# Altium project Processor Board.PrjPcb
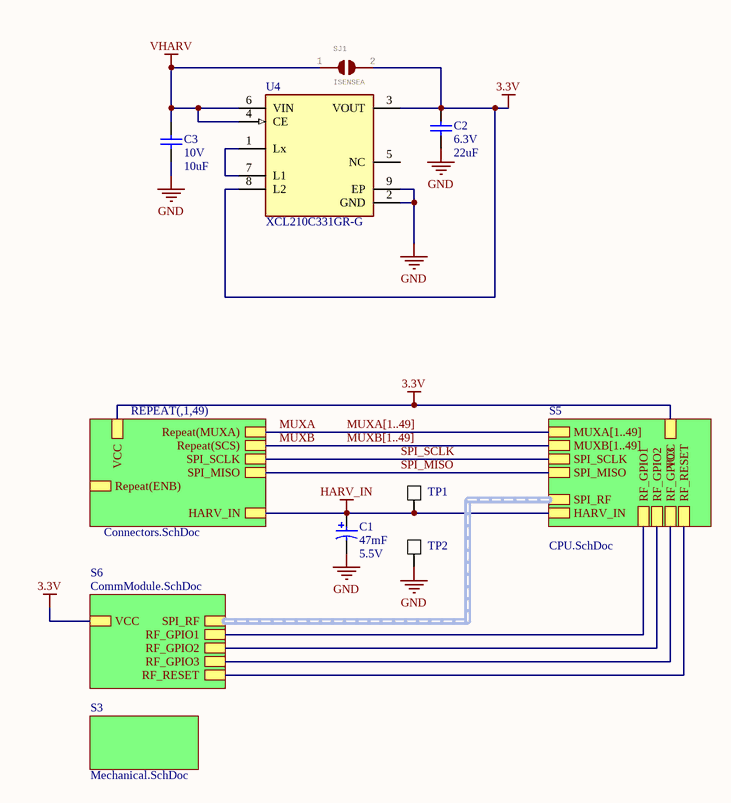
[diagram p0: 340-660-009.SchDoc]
ASSM_PN: Set In Variant; BOM_REV: 1.0.0; DOC_NUM: 340-660-009; DOC_REV: 1.0.0; PCB_PN: 21000-1011
5 sheets, 186 parts. Net scope: hierarchical (ports join the sheet entries above them; power ports are global).
Board file: 340-660-009.PcbDoc
Sheets:
  340-660-009.SchDoc
    S3 = Mechanical.SchDoc
    1 = Connectors.SchDoc
    2 = Connectors.SchDoc
    3 = Connectors.SchDoc
    4 = Connectors.SchDoc
    5 = Connectors.SchDoc
    6 = Connectors.SchDoc
    7 = Connectors.SchDoc
    8 = Connectors.SchDoc
    9 = Connectors.SchDoc
    10 = Connectors.SchDoc
    11 = Connectors.SchDoc
    12 = Connectors.SchDoc
    13 = Connectors.SchDoc
    14 = Connectors.SchDoc
    15 = Connectors.SchDoc
    16 = Connectors.SchDoc
    17 = Connectors.SchDoc
    18 = Connectors.SchDoc
    19 = Connectors.SchDoc
    20 = Connectors.SchDoc
    21 = Connectors.SchDoc
    22 = Connectors.SchDoc
    23 = Connectors.SchDoc
    24 = Connectors.SchDoc
    25 = Connectors.SchDoc
    26 = Connectors.SchDoc
    27 = Connectors.SchDoc
    28 = Connectors.SchDoc
    29 = Connectors.SchDoc
    30 = Connectors.SchDoc
    31 = Connectors.SchDoc
    32 = Connectors.SchDoc
    33 = Connectors.SchDoc
    34 = Connectors.SchDoc
    35 = Connectors.SchDoc
    36 = Connectors.SchDoc
    37 = Connectors.SchDoc
    38 = Connectors.SchDoc
    39 = Connectors.SchDoc
    40 = Connectors.SchDoc
    41 = Connectors.SchDoc
    42 = Connectors.SchDoc
    43 = Connectors.SchDoc
    44 = Connectors.SchDoc
    45 = Connectors.SchDoc
    46 = Connectors.SchDoc
    47 = Connectors.SchDoc
    48 = Connectors.SchDoc
    49 = Connectors.SchDoc
    S5 = CPU.SchDoc
    S6 = CommModule.SchDoc

## Sheet 340-660-009.SchDoc
size A; SheetNumber: 1; SheetTotal: 5

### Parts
C1  value 47mF  Voltage: 5.5V  [CAP_KEM_S6011_FC]  (hidden comment: FCS0H473ZFTBR24)
C2  value 22uF  Voltage: 6.3V  [0402CAP]  (hidden comment: CL05A226MQ6ZUN8)
C3  value 10uF  Voltage: 10V  [0402CAP]  (hidden comment: CL05A106MP5NUNC)
SJ1  ISENSEA  [SOLDERJUMPER_ARROW_NOPASTE]  (no BOM)
TP1  TEST POINT  [TP1-s]  (value not drawn)  (no BOM)
TP2  TEST POINT  [TP1-s]  (value not drawn)  (no BOM)
U4  XCL210C331GR-G  [XCL210C331GRG]

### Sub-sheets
REPEAT(,1,49) = Connectors.SchDoc: Repeat(MUXA), HARV_IN, VCC, Repeat(ENB), Repeat(SCS), SPI_SCLK, SPI_MISO
S3 = Mechanical.SchDoc: no entries
S5 = CPU.SchDoc: VCC, SPI_RF (harness SPI), HARV_IN, MUXA[1..49], MUXB[1..49], SPI_SCLK, SPI_MISO, RF_GPIO1, RF_GPIO2, RF_GPIO3, RF_RESET
S6 = CommModule.SchDoc: VCC, SPI_RF (harness SPI), RF_GPIO1, RF_GPIO2, RF_GPIO3, RF_RESET

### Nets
3.3V: C2.2 SJ1.2 U4.3(VOUT) U4.8(L2) ; sheet REPEAT(,1,49)/VCC, sheet S5/VCC, sheet S6/VCC  [project net V3.3V]
GND: C1.- C2.1 C3.1 TP2.1(A) U4.2(GND) U4.9(EP)
HARV_IN: C1.+ TP1.1(A) ; sheet REPEAT(,1,49)/HARV_IN, sheet S5/HARV_IN
VHARV: C3.2 SJ1.1 U4.4(CE) U4.6(VIN)
DIO1: sheet S5/RF_GPIO3, sheet S6/RF_GPIO3
DIO2: sheet S5/RF_GPIO2, sheet S6/RF_GPIO2
DIO3: sheet S5/RF_GPIO1, sheet S6/RF_GPIO1
nRESET: sheet S5/RF_RESET, sheet S6/RF_RESET
SPI_MISO: sheet REPEAT(,1,49)/SPI_MISO, sheet S5/SPI_MISO
SPI_SCLK: sheet REPEAT(,1,49)/SPI_SCLK, sheet S5/SPI_SCLK
NetU4_1: U4.1(Lx) U4.7(L1)

Not connected (* = marked no-connect by the designer): U4 5(NC)

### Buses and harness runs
bus MUXA[1..49] = sheet S5/MUXA[1..49]
bus MUXB[1..49] = sheet S5/MUXB[1..49]
harness sheet S5/SPI_RF = sheet S6/SPI_RF

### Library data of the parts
C1 = CAP_Supercap_47mF_5.5V_FCS0H473ZFTBR24: 47 mF (EDLC) Supercapacitor 5.5 V Radial, Can - SMD 100Ohm @ 1kHz; Mfg: Kemet; ADSP_PN: 17015-???
C2 = CAP_0402_22uF_X5R_6.3V: 22µF ±20% 6.3V Ceramic Capacitor X5R 0402 (1005 Metric); ADSP_PN: 01020-158; Mfg: Samsung
C3 = CAP_0402_10uF_X5R_10V: CAP CER 10UF 10V X5R 0402; ADSP_PN: 01020-053; Mfg: Samsung; Type: CAPACITOR
SJ1 = SOLDERJUMPER_OPEN: SMD Solder JUMPER   Solder the two pads together to create a connection, or remove the solder to break it.REFLOW - Use this footprint for solder paste and reflow ovens. WAVE - Use this footprint for hand-soldering (larger pads).    CLOSED - Has a trace between the two pads to ensure it is closed by default.  The trace needs to be cut to disable the jumper, and can be closed again by creating a solder bridge between the two pads.; GateName_1: 1; BOM: EXCLUDE
TP1 TP2 = Test_Point_SMT: Test Point SMT
U4 = XCL210C331GR-G: DC/DC CONV, 3.3V, 0.2A, 85DEG C ROHS COMPLIANT: YES; Mfg: Torex

## Sheet Mechanical.SchDoc
size A; SheetNumber: 2; SheetTotal: 5
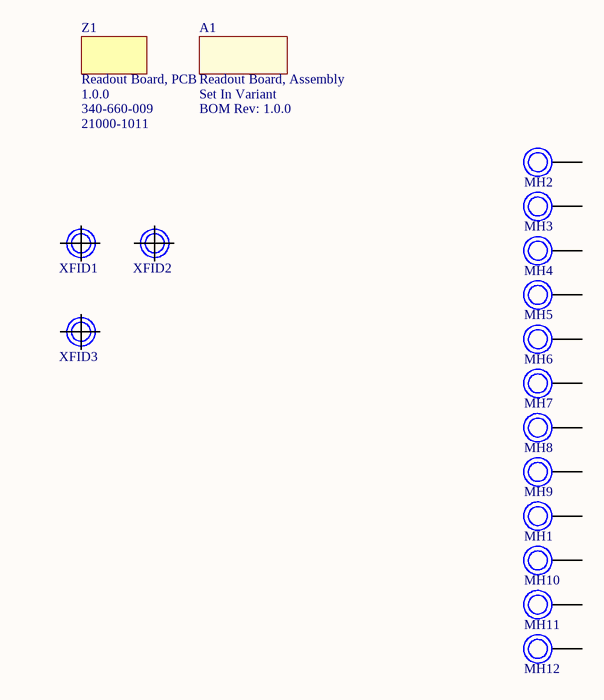
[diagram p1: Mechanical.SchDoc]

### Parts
A1  Readout Board, Assembly  BOM Rev: 1.0.0  ADSP_PN: Set In Variant  (mechanical)
MH1  Mounting Hole  [MH_2MM]  (value not drawn)  (no BOM)
MH2  Mounting Hole  [MH_2MM]  (value not drawn)  (no BOM)
MH3  Mounting Hole  [MH_2MM]  (value not drawn)  (no BOM)
MH4  Mounting Hole  [MH_2MM]  (value not drawn)  (no BOM)
MH5  Mounting Hole  [MH_2MM]  (value not drawn)  (no BOM)
MH6  Mounting Hole  [MH_2MM]  (value not drawn)  (no BOM)
MH7  Mounting Hole  [MH_2MM]  (value not drawn)  (no BOM)
MH8  Mounting Hole  [MH_2MM]  (value not drawn)  (no BOM)
MH9  Mounting Hole  [MH_2MM]  (value not drawn)  (no BOM)
MH10  Mounting Hole  [MH_2MM]  (value not drawn)  (no BOM)
MH11  Mounting Hole  [MH_2MM]  (value not drawn)  (no BOM)
MH12  Mounting Hole  [MH_2MM]  (value not drawn)  (no BOM)
XFID1  (no value)  [FID_TOP_BOT_39]
XFID2  (no value)  [FID_TOP_BOT_39]
XFID3  (no value)  [FID_TOP_BOT_39]
Z1  Readout Board, PCB  Rev: 1.0.0  DocNum: 340-660-009  ADSP_PN: 21000-1011  (mechanical)

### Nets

Not connected (* = marked no-connect by the designer): MH1 1; MH2 1; MH3 1; MH4 1; MH5 1; MH6 1; MH7 1; MH8 1; MH9 1; MH10 1; MH11 1; MH12 1

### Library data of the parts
A1 = PCB_Assembly: DocNum: 340-660-009
MH1-MH12 = MountingHole
XFID1-XFID3 = MOUNT_FIDUCIAL: Mounting Hole
Z1 = PCB_Rigid: RIGID PCB;  BARE

## Sheet Connectors.SchDoc
size A; SheetNumber: 4; SheetTotal: 5
Used 49 times, as channels 1, 2, 3, 4, 5, 6, 7, 8, 9, 10, 11, 12, 13, 14, 15, 16, 17, 18, 19, 20, 21, 22, 23, 24, 25, 26, 27, 28, 29, 30, 31, 32, 33, 34, 35, 36, 37, 38, 39, 40, 41, 42, 43, 44, 45, 46, 47, 48, 49. Parts and nets are listed once, with the designators drawn on the sheet.
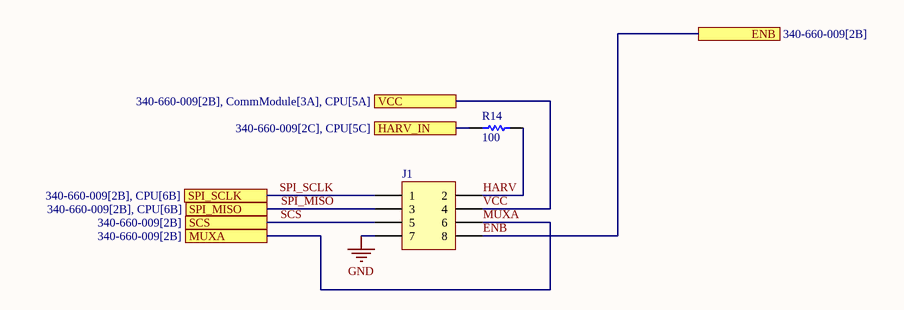
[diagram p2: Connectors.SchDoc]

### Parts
J1  (no value)  [CONN_SAMTEC_FTS-104-01-L-DV]
R14  value 100  [0402RES]  (hidden comment: RC0402FR-07100RL)

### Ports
ENB (see 340-660-009[2B]), HARV_IN (see 340-660-009[2C], CPU[5C]), MUXA (see 340-660-009[2B]), SCS (see 340-660-009[2B]), SPI_MISO (see 340-660-009[2B], CPU[6B]), SPI_SCLK (see 340-660-009[2B], CPU[6B]), VCC (see 340-660-009[2B], CommModule[3A], CPU[5A])

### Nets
GND: J1.7
ENB: J1.8 ; port ENB
HARV: J1.2 R14.1
HARV_IN: R14.2 ; port HARV_IN
MUXA: J1.6 ; port MUXA
SCS: J1.5 ; port SCS
SPI_MISO: J1.3 ; port SPI_MISO
SPI_SCLK: J1.1 ; port SPI_SCLK
VCC: J1.4 ; port VCC

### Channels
1: designators J1=J2#1 R14=R4#1; ports ENB=ENB_1 HARV_IN=HARV_IN MUXA=MUXA SCS=MUXB1 SPI_MISO=SPI_MISO SPI_SCLK=SPI_SCLK VCC=V3.3V
2: designators J1=J3#1 R14=R5#1; ports ENB=ENB_2 HARV_IN=HARV_IN MUXA=MUXA SCS=MUXB2 SPI_MISO=SPI_MISO SPI_SCLK=SPI_SCLK VCC=V3.3V
3: designators J1=J4#1 R14=R6; ports ENB=ENB_3 HARV_IN=HARV_IN MUXA=MUXA SCS=MUXB3 SPI_MISO=SPI_MISO SPI_SCLK=SPI_SCLK VCC=V3.3V
4: designators J1=J5#1 R14=R7; ports ENB=ENB_4 HARV_IN=HARV_IN MUXA=MUXA SCS=MUXB4 SPI_MISO=SPI_MISO SPI_SCLK=SPI_SCLK VCC=V3.3V
5: designators J1=J6 R14=R8#1; ports ENB=ENB_5 HARV_IN=HARV_IN MUXA=MUXA SCS=MUXB5 SPI_MISO=SPI_MISO SPI_SCLK=SPI_SCLK VCC=V3.3V
6: designators J1=J7 R14=R9#1; ports ENB=ENB_6 HARV_IN=HARV_IN MUXA=MUXA SCS=MUXB6 SPI_MISO=SPI_MISO SPI_SCLK=SPI_SCLK VCC=V3.3V
7: designators J1=J8 R14=R10#1; ports ENB=ENB_7 HARV_IN=HARV_IN MUXA=MUXA SCS=MUXB7 SPI_MISO=SPI_MISO SPI_SCLK=SPI_SCLK VCC=V3.3V
8: designators J1=J9 R14=R11; ports ENB=ENB_8 HARV_IN=HARV_IN MUXA=MUXA SCS=MUXB8 SPI_MISO=SPI_MISO SPI_SCLK=SPI_SCLK VCC=V3.3V
9: designators J1=J10 R14=R12; ports ENB=ENB_9 HARV_IN=HARV_IN MUXA=MUXA SCS=MUXB9 SPI_MISO=SPI_MISO SPI_SCLK=SPI_SCLK VCC=V3.3V
10: designators J1=J11 R14=R13; ports ENB=ENB_10 HARV_IN=HARV_IN MUXA=MUXA SCS=MUXB10 SPI_MISO=SPI_MISO SPI_SCLK=SPI_SCLK VCC=V3.3V
11: designators J1=J12 R14=R14; ports ENB=ENB_11 HARV_IN=HARV_IN MUXA=MUXA SCS=MUXB11 SPI_MISO=SPI_MISO SPI_SCLK=SPI_SCLK VCC=V3.3V
12: designators J1=J13 R14=R15; ports ENB=ENB_12 HARV_IN=HARV_IN MUXA=MUXA SCS=MUXB12 SPI_MISO=SPI_MISO SPI_SCLK=SPI_SCLK VCC=V3.3V
13: designators J1=J14 R14=R16; ports ENB=ENB_13 HARV_IN=HARV_IN MUXA=MUXA SCS=MUXB13 SPI_MISO=SPI_MISO SPI_SCLK=SPI_SCLK VCC=V3.3V
14: designators J1=J15 R14=R17; ports ENB=ENB_14 HARV_IN=HARV_IN MUXA=MUXA SCS=MUXB14 SPI_MISO=SPI_MISO SPI_SCLK=SPI_SCLK VCC=V3.3V
15: designators J1=J16 R14=R18; ports ENB=ENB_15 HARV_IN=HARV_IN MUXA=MUXA SCS=MUXB15 SPI_MISO=SPI_MISO SPI_SCLK=SPI_SCLK VCC=V3.3V
16: designators J1=J17 R14=R19; ports ENB=ENB_16 HARV_IN=HARV_IN MUXA=MUXA SCS=MUXB16 SPI_MISO=SPI_MISO SPI_SCLK=SPI_SCLK VCC=V3.3V
17: designators J1=J18 R14=R20; ports ENB=ENB_17 HARV_IN=HARV_IN MUXA=MUXA SCS=MUXB17 SPI_MISO=SPI_MISO SPI_SCLK=SPI_SCLK VCC=V3.3V
18: designators J1=J19 R14=R21; ports ENB=ENB_18 HARV_IN=HARV_IN MUXA=MUXA SCS=MUXB18 SPI_MISO=SPI_MISO SPI_SCLK=SPI_SCLK VCC=V3.3V
19: designators J1=J20 R14=R22; ports ENB=ENB_19 HARV_IN=HARV_IN MUXA=MUXA SCS=MUXB19 SPI_MISO=SPI_MISO SPI_SCLK=SPI_SCLK VCC=V3.3V
20: designators J1=J21 R14=R23; ports ENB=ENB_20 HARV_IN=HARV_IN MUXA=MUXA SCS=MUXB20 SPI_MISO=SPI_MISO SPI_SCLK=SPI_SCLK VCC=V3.3V
21: designators J1=J22 R14=R24; ports ENB=ENB_21 HARV_IN=HARV_IN MUXA=MUXA SCS=MUXB21 SPI_MISO=SPI_MISO SPI_SCLK=SPI_SCLK VCC=V3.3V
22: designators J1=J23 R14=R25; ports ENB=ENB_22 HARV_IN=HARV_IN MUXA=MUXA SCS=MUXB22 SPI_MISO=SPI_MISO SPI_SCLK=SPI_SCLK VCC=V3.3V
23: designators J1=J24 R14=R26; ports ENB=ENB_23 HARV_IN=HARV_IN MUXA=MUXA SCS=MUXB23 SPI_MISO=SPI_MISO SPI_SCLK=SPI_SCLK VCC=V3.3V
24: designators J1=J25 R14=R27; ports ENB=ENB_24 HARV_IN=HARV_IN MUXA=MUXA SCS=MUXB24 SPI_MISO=SPI_MISO SPI_SCLK=SPI_SCLK VCC=V3.3V
25: designators J1=J26 R14=R28; ports ENB=ENB_25 HARV_IN=HARV_IN MUXA=MUXA SCS=MUXB25 SPI_MISO=SPI_MISO SPI_SCLK=SPI_SCLK VCC=V3.3V
26: designators J1=J27 R14=R29; ports ENB=ENB_26 HARV_IN=HARV_IN MUXA=MUXA SCS=MUXB26 SPI_MISO=SPI_MISO SPI_SCLK=SPI_SCLK VCC=V3.3V
27: designators J1=J28 R14=R30; ports ENB=ENB_27 HARV_IN=HARV_IN MUXA=MUXA SCS=MUXB27 SPI_MISO=SPI_MISO SPI_SCLK=SPI_SCLK VCC=V3.3V
28: designators J1=J29 R14=R31; ports ENB=ENB_28 HARV_IN=HARV_IN MUXA=MUXA SCS=MUXB28 SPI_MISO=SPI_MISO SPI_SCLK=SPI_SCLK VCC=V3.3V
29: designators J1=J30 R14=R32; ports ENB=ENB_29 HARV_IN=HARV_IN MUXA=MUXA SCS=MUXB29 SPI_MISO=SPI_MISO SPI_SCLK=SPI_SCLK VCC=V3.3V
30: designators J1=J31 R14=R33; ports ENB=ENB_30 HARV_IN=HARV_IN MUXA=MUXA SCS=MUXB30 SPI_MISO=SPI_MISO SPI_SCLK=SPI_SCLK VCC=V3.3V
31: designators J1=J32 R14=R34; ports ENB=ENB_31 HARV_IN=HARV_IN MUXA=MUXA SCS=MUXB31 SPI_MISO=SPI_MISO SPI_SCLK=SPI_SCLK VCC=V3.3V
32: designators J1=J33 R14=R35; ports ENB=ENB_32 HARV_IN=HARV_IN MUXA=MUXA SCS=MUXB32 SPI_MISO=SPI_MISO SPI_SCLK=SPI_SCLK VCC=V3.3V
33: designators J1=J34 R14=R36; ports ENB=ENB_33 HARV_IN=HARV_IN MUXA=MUXA SCS=MUXB33 SPI_MISO=SPI_MISO SPI_SCLK=SPI_SCLK VCC=V3.3V
34: designators J1=J35 R14=R37; ports ENB=ENB_34 HARV_IN=HARV_IN MUXA=MUXA SCS=MUXB34 SPI_MISO=SPI_MISO SPI_SCLK=SPI_SCLK VCC=V3.3V
35: designators J1=J36 R14=R38; ports ENB=ENB_35 HARV_IN=HARV_IN MUXA=MUXA SCS=MUXB35 SPI_MISO=SPI_MISO SPI_SCLK=SPI_SCLK VCC=V3.3V
36: designators J1=J37 R14=R39; ports ENB=ENB_36 HARV_IN=HARV_IN MUXA=MUXA SCS=MUXB36 SPI_MISO=SPI_MISO SPI_SCLK=SPI_SCLK VCC=V3.3V
37: designators J1=J38 R14=R40; ports ENB=ENB_37 HARV_IN=HARV_IN MUXA=MUXA SCS=MUXB37 SPI_MISO=SPI_MISO SPI_SCLK=SPI_SCLK VCC=V3.3V
38: designators J1=J39 R14=R41; ports ENB=ENB_38 HARV_IN=HARV_IN MUXA=MUXA SCS=MUXB38 SPI_MISO=SPI_MISO SPI_SCLK=SPI_SCLK VCC=V3.3V
39: designators J1=J40 R14=R42; ports ENB=ENB_39 HARV_IN=HARV_IN MUXA=MUXA SCS=MUXB39 SPI_MISO=SPI_MISO SPI_SCLK=SPI_SCLK VCC=V3.3V
40: designators J1=J41 R14=R43; ports ENB=ENB_40 HARV_IN=HARV_IN MUXA=MUXA SCS=MUXB40 SPI_MISO=SPI_MISO SPI_SCLK=SPI_SCLK VCC=V3.3V
41: designators J1=J42 R14=R44; ports ENB=ENB_41 HARV_IN=HARV_IN MUXA=MUXA SCS=MUXB41 SPI_MISO=SPI_MISO SPI_SCLK=SPI_SCLK VCC=V3.3V
42: designators J1=J43 R14=R45; ports ENB=ENB_42 HARV_IN=HARV_IN MUXA=MUXA SCS=MUXB42 SPI_MISO=SPI_MISO SPI_SCLK=SPI_SCLK VCC=V3.3V
43: designators J1=J44 R14=R46; ports ENB=ENB_43 HARV_IN=HARV_IN MUXA=MUXA SCS=MUXB43 SPI_MISO=SPI_MISO SPI_SCLK=SPI_SCLK VCC=V3.3V
44: designators J1=J45 R14=R47; ports ENB=ENB_44 HARV_IN=HARV_IN MUXA=MUXA SCS=MUXB44 SPI_MISO=SPI_MISO SPI_SCLK=SPI_SCLK VCC=V3.3V
45: designators J1=J46 R14=R48; ports ENB=ENB_45 HARV_IN=HARV_IN MUXA=MUXA SCS=MUXB45 SPI_MISO=SPI_MISO SPI_SCLK=SPI_SCLK VCC=V3.3V
46: designators J1=J47 R14=R49; ports ENB=ENB_46 HARV_IN=HARV_IN MUXA=MUXA SCS=MUXB46 SPI_MISO=SPI_MISO SPI_SCLK=SPI_SCLK VCC=V3.3V
47: designators J1=J48 R14=R50; ports ENB=ENB_47 HARV_IN=HARV_IN MUXA=MUXA SCS=MUXB47 SPI_MISO=SPI_MISO SPI_SCLK=SPI_SCLK VCC=V3.3V
48: designators J1=J49 R14=R51; ports ENB=ENB_48 HARV_IN=HARV_IN MUXA=MUXA SCS=MUXB48 SPI_MISO=SPI_MISO SPI_SCLK=SPI_SCLK VCC=V3.3V
49: designators J1=J51 R14=R56; ports ENB=ENB_49 HARV_IN=HARV_IN MUXA=MUXA SCS=MUXB49 SPI_MISO=SPI_MISO SPI_SCLK=SPI_SCLK VCC=V3.3V

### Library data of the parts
J1 = CONN_Samtec_FTS-104-01-L-DV: 2x4 0.050" Surface Mount Micro Terminal Strip; Positions: 6; Gender: MALE; Mfg: Samtec; Mfg_PN: FTS-103-01-L-DV; ADSP_PN: 03000-???
R14 = Res_0402_100_1%_1: RES SMD 100 OHM 1% 1/16W 0402; ADSP_PN: 00100-160; Mfg: Yageo

## Sheet CPU.SchDoc
size B; SheetNumber: 5; SheetTotal: 5
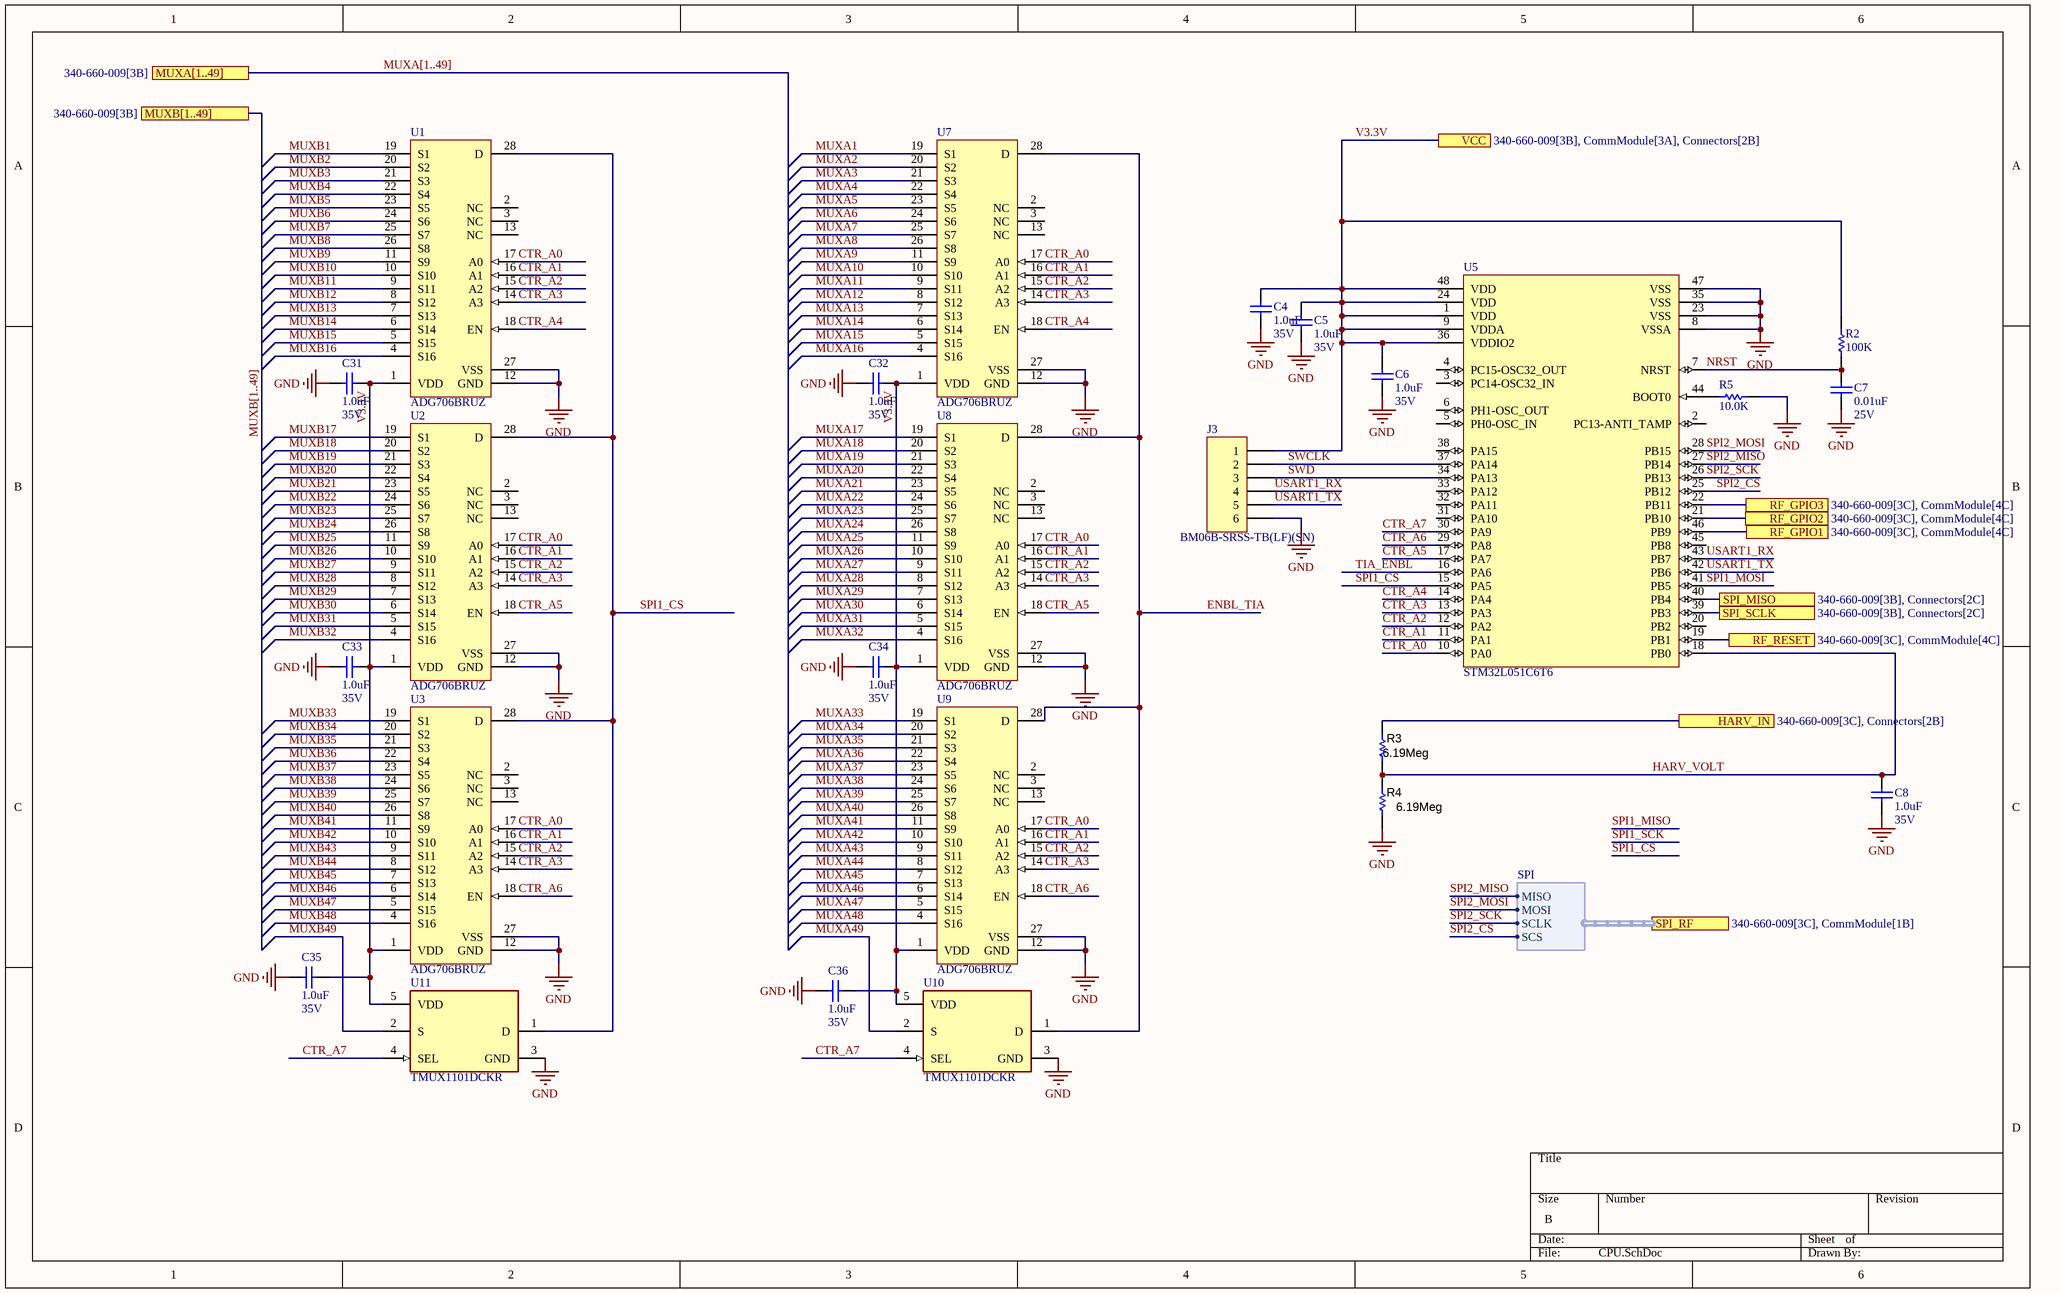
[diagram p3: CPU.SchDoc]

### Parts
(Parts that share a designator on the sheet are numbered #1, #2 ... from top to bottom, then left to right.)
C4  value 1.0uF  Voltage: 35V  [0402CAP]  (hidden comment: C1005X5R1V105K050BC)
C5  value 1.0uF  Voltage: 35V  [0402CAP]  (hidden comment: C1005X5R1V105K050BC)
C6  value 1.0uF  Voltage: 35V  [0402CAP]  (hidden comment: C1005X5R1V105K050BC)
C7  value 0.01uF  Voltage: 25V  [0402CAP]  (hidden comment: ECJ-0EB1E103K)
C8  value 1.0uF  Voltage: 35V  [0402CAP]  (hidden comment: C1005X5R1V105K050BC)
C31  value 1.0uF  Voltage: 35V  [0402CAP]  (hidden comment: C1005X5R1V105K050BC)
C32  value 1.0uF  Voltage: 35V  [0402CAP]  (hidden comment: C1005X5R1V105K050BC)
C33  value 1.0uF  Voltage: 35V  [0402CAP]  (hidden comment: C1005X5R1V105K050BC)
C34  value 1.0uF  Voltage: 35V  [0402CAP]  (hidden comment: C1005X5R1V105K050BC)
C35  value 1.0uF  Voltage: 35V  [0402CAP]  (hidden comment: C1005X5R1V105K050BC)
C36  value 1.0uF  Voltage: 35V  [0402CAP]  (hidden comment: C1005X5R1V105K050BC)
J3#2  BM06B-SRSS-TB(LF)(SN)  [JST_BM06B_TOP]
R2  value 100K  [0402RES]  (hidden comment: RC0402FR-07100KL)
R3  value 6.19Meg  [0402RES]
R4#2  value 6.19Meg  [0402RES]
R5#2  value 10.0K  [0402RES_SM]  (hidden comment: CRCW040210K0FKEDHP)
U1  ADG706BRUZ  [ADI-RU-28_L]
U2  ADG706BRUZ  [ADI-RU-28_L]
U3  ADG706BRUZ  [ADI-RU-28_L]
U5  STM32L051C6T6  [STM-LQFP48_N]
U7  ADG706BRUZ  [ADI-RU-28_L]
U8  ADG706BRUZ  [ADI-RU-28_L]
U9  ADG706BRUZ  [ADI-RU-28_L]
U10  TMUX1101DCKR  [FP-DCK0005A-IPC_B]
U11  TMUX1101DCKR  [FP-DCK0005A-IPC_B]

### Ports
HARV_IN (see 340-660-009[3C], Connectors[2B]), MUXA[1..49] (see 340-660-009[3B]), MUXB[1..49] (see 340-660-009[3B]), RF_GPIO1 (see 340-660-009[3C], CommModule[4C]), RF_GPIO2 (see 340-660-009[3C], CommModule[4C]), RF_GPIO3 (see 340-660-009[3C], CommModule[4C]), RF_RESET (see 340-660-009[3C], CommModule[4C]), SPI_MISO (see 340-660-009[3B], Connectors[2C]), SPI_RF (harness SPI, see 340-660-009[3C], CommModule[1B]), SPI_SCLK (see 340-660-009[3B], Connectors[2C]), VCC (see 340-660-009[3B], CommModule[3A], Connectors[2B])

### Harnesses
SPI: MISO, MOSI, SCLK, SCS

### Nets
GND: C4.1 C5.1 C6.1 C7.1 C8.1 C31.1 C32.1 C33.1 C34.1 C35.1 C36.1 J3#2.6 R4#2.1 R5#2.2 U1.12(GND) U1.27(VSS) U2.12(GND) U2.27(VSS) U3.12(GND) U3.27(VSS) U5.8(VSSA) U5.23(VSS) U5.35(VSS) U5.47(VSS) U7.12(GND) U7.27(VSS) U8.12(GND) U8.27(VSS) U9.12(GND) U9.27(VSS) U10.3(GND) U11.3(GND)
HARV_IN: R3.2 ; port HARV_IN
V3.3V: C4.2 C5.2 C6.2 C31.2 C32.2 C33.2 C34.2 C35.2 C36.2 J3#2.1 R2.2 U1.1(VDD) U2.1(VDD) U3.1(VDD) U5.1(VDD) U5.9(VDDA) U5.24(VDD) U5.36(VDDIO2) U5.48(VDD) U7.1(VDD) U8.1(VDD) U9.1(VDD) U10.5(VDD) U11.5(VDD) ; port VCC
CTR_A0: U1.17(A0) U2.17(A0) U3.17(A0) U5.10(PA0) U7.17(A0) U8.17(A0) U9.17(A0)
CTR_A1: U1.16(A1) U2.16(A1) U3.16(A1) U5.11(PA1) U7.16(A1) U8.16(A1) U9.16(A1)
CTR_A2: U1.15(A2) U2.15(A2) U3.15(A2) U5.12(PA2) U7.15(A2) U8.15(A2) U9.15(A2)
CTR_A3: U1.14(A3) U2.14(A3) U3.14(A3) U5.13(PA3) U7.14(A3) U8.14(A3) U9.14(A3)
CTR_A4: U1.18(EN) U5.14(PA4) U7.18(EN)
CTR_A5: U2.18(EN) U5.17(PA7) U8.18(EN)
CTR_A6: U3.18(EN) U5.29(PA8) U9.18(EN)
CTR_A7: U5.30(PA9) U10.4(SEL) U11.4(SEL)
DIO1: U5.22(PB11) ; port RF_GPIO3
DIO2: U5.21(PB10) ; port RF_GPIO2
DIO3: U5.46(PB9) ; port RF_GPIO1
ENBL_TIA: U7.28(D) U8.28(D) U9.28(D) U10.1(D)
HARV_VOLT: C8.2 R3.1 R4#2.2 U5.18(PB0)
MUXA1: U7.19(S1)  [project net MUXA]
MUXA2: U7.20(S2)  [project net MUXA]
MUXA3: U7.21(S3)  [project net MUXA]
MUXA4: U7.22(S4)  [project net MUXA]
MUXA5: U7.23(S5)  [project net MUXA]
MUXA6: U7.24(S6)  [project net MUXA]
MUXA7: U7.25(S7)  [project net MUXA]
MUXA8: U7.26(S8)  [project net MUXA]
MUXA9: U7.11(S9)  [project net MUXA]
MUXA10: U7.10(S10)  [project net MUXA]
MUXA11: U7.9(S11)  [project net MUXA]
MUXA12: U7.8(S12)  [project net MUXA]
MUXA13: U7.7(S13)  [project net MUXA]
MUXA14: U7.6(S14)  [project net MUXA]
MUXA15: U7.5(S15)  [project net MUXA]
MUXA16: U7.4(S16)  [project net MUXA]
MUXA17: U8.19(S1)  [project net MUXA]
MUXA18: U8.20(S2)  [project net MUXA]
MUXA19: U8.21(S3)  [project net MUXA]
MUXA20: U8.22(S4)  [project net MUXA]
MUXA21: U8.23(S5)  [project net MUXA]
MUXA22: U8.24(S6)  [project net MUXA]
MUXA23: U8.25(S7)  [project net MUXA]
MUXA24: U8.26(S8)  [project net MUXA]
MUXA25: U8.11(S9)  [project net MUXA]
MUXA26: U8.10(S10)  [project net MUXA]
MUXA27: U8.9(S11)  [project net MUXA]
MUXA28: U8.8(S12)  [project net MUXA]
MUXA29: U8.7(S13)  [project net MUXA]
MUXA30: U8.6(S14)  [project net MUXA]
MUXA31: U8.5(S15)  [project net MUXA]
MUXA32: U8.4(S16)  [project net MUXA]
MUXA33: U9.19(S1)  [project net MUXA]
MUXA34: U9.20(S2)  [project net MUXA]
MUXA35: U9.21(S3)  [project net MUXA]
MUXA36: U9.22(S4)  [project net MUXA]
MUXA37: U9.23(S5)  [project net MUXA]
MUXA38: U9.24(S6)  [project net MUXA]
MUXA39: U9.25(S7)  [project net MUXA]
MUXA40: U9.26(S8)  [project net MUXA]
MUXA41: U9.11(S9)  [project net MUXA]
MUXA42: U9.10(S10)  [project net MUXA]
MUXA43: U9.9(S11)  [project net MUXA]
MUXA44: U9.8(S12)  [project net MUXA]
MUXA45: U9.7(S13)  [project net MUXA]
MUXA46: U9.6(S14)  [project net MUXA]
MUXA47: U9.5(S15)  [project net MUXA]
MUXA48: U9.4(S16)  [project net MUXA]
MUXA49: U10.2(S)  [project net MUXA]
MUXB1: U1.19(S1)
MUXB2: U1.20(S2)
MUXB3: U1.21(S3)
MUXB4: U1.22(S4)
MUXB5: U1.23(S5)
MUXB6: U1.24(S6)
MUXB7: U1.25(S7)
MUXB8: U1.26(S8)
MUXB9: U1.11(S9)
MUXB10: U1.10(S10)
MUXB11: U1.9(S11)
MUXB12: U1.8(S12)
MUXB13: U1.7(S13)
MUXB14: U1.6(S14)
MUXB15: U1.5(S15)
MUXB16: U1.4(S16)
MUXB17: U2.19(S1)
MUXB18: U2.20(S2)
MUXB19: U2.21(S3)
MUXB20: U2.22(S4)
MUXB21: U2.23(S5)
MUXB22: U2.24(S6)
MUXB23: U2.25(S7)
MUXB24: U2.26(S8)
MUXB25: U2.11(S9)
MUXB26: U2.10(S10)
MUXB27: U2.9(S11)
MUXB28: U2.8(S12)
MUXB29: U2.7(S13)
MUXB30: U2.6(S14)
MUXB31: U2.5(S15)
MUXB32: U2.4(S16)
MUXB33: U3.19(S1)
MUXB34: U3.20(S2)
MUXB35: U3.21(S3)
MUXB36: U3.22(S4)
MUXB37: U3.23(S5)
MUXB38: U3.24(S6)
MUXB39: U3.25(S7)
MUXB40: U3.26(S8)
MUXB41: U3.11(S9)
MUXB42: U3.10(S10)
MUXB43: U3.9(S11)
MUXB44: U3.8(S12)
MUXB45: U3.7(S13)
MUXB46: U3.6(S14)
MUXB47: U3.5(S15)
MUXB48: U3.4(S16)
MUXB49: U11.2(S)
nRESET: U5.19(PB1) ; port RF_RESET
NRST: C7.2 R2.1 U5.7(NRST)
SPI1_CS: U1.28(D) U2.28(D) U3.28(D) U5.15(PA5) U11.1(D)
SPI1_MOSI: U5.41(PB5)
SPI2_CS: U5.25(PB12) ; port SPI_RF.SCS
SPI2_MISO: U5.27(PB14) ; port SPI_RF.MISO
SPI2_MOSI: U5.28(PB15) ; port SPI_RF.MOSI
SPI2_SCK: U5.26(PB13) ; port SPI_RF.SCLK
SPI_MISO: U5.40(PB4) ; port SPI_MISO
SPI_SCLK: U5.39(PB3) ; port SPI_SCLK
SWCLK: J3#2.2 U5.37(PA14)
SWD: J3#2.3 U5.34(PA13)
TIA_ENBL: U5.16(PA6)
USART1_RX: J3#2.4 U5.43(PB7)
USART1_TX: J3#2.5 U5.42(PB6)
NetR5#2_1: R5#2.1 U5.44(BOOT0)

Not connected (* = marked no-connect by the designer): U1 2(NC) 3(NC) 13(NC); U2 2(NC) 3(NC) 13(NC); U3 2(NC) 3(NC) 13(NC); U5 2(PC13-ANTI_TAMP) 3(PC14-OSC32_IN) 4(PC15-OSC32_OUT) 5(PH0-OSC_IN) 6(PH1-OSC_OUT) 20(PB2) 31(PA10) 32(PA11) 33(PA12) 38(PA15) 45(PB8); U7 2(NC) 3(NC) 13(NC); U8 2(NC) 3(NC) 13(NC); U9 2(NC) 3(NC) 13(NC)

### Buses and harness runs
bus MUXA[1..49] = port MUXA[1..49]
bus MUXB[1..49] = port MUXB[1..49]

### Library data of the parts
C4-C6 C8 C31-C36 = CAP_0402_1uF_X5R_35V: CAP CER 1UF 35V X5R 0402; ADSP_PN: 01020-039; Mfg: TDK; Type: CAPACITOR
C7 = CAP_0402_0.01uF_X7R_25V_2: CAP .01UF 25V CERAMIC X7R 0402; ADSP_PN: 01010-047; Mfg: Panasonic; Type: CAPACITOR
J3#2 = CONN_JST-BM06B-SRSS-TB: CONN HEADER SH 6POS TOP 1MM TIN; Mfg: JST; Positions: 6; ADSP_PN: 03000-190
R2 = Res_0402_100K_1%: RES 100K OHM 1/16W 1% 0402 SMD; ADSP_PN: 00100-028; Mfg: Yageo
R3 R4#2 = Res_0402_6.19MEG_1%: RES, 6.19 M, 1%, 0.063 W, 0402; Part: CRCW04026M19FKED; Mfg: Vishay-Dale; Power: 0.063W; ADSP_PN: 00100-???
R5#2 = Res_0402_10.0K_1%: RES 10K OHM 1/10W 1% 0402 SMD; ADSP_PN: 00100-161; Mfg: Vishay
U1-U3 U7-U9 = CMP-0798-00225-1: 1.8 to 5.5 V / 2.5 V, CMOS Low-Voltage 2.5 Ohm, 16-Channel Multiplexer, -40 to 85 degC, 28-pin SOP (RU-28), Tube; Manufacturer: Analog Devices; t transition (s): 40n; Ron (ohms): 2.5; Bandwidth (Hz): 25M; Supply V Guar Performance: Dual_(+/-2.5V), Single_(+3V), Single_(+5V); Max Analog Signal Range: Vss to Vdd
U5 = CMP-1546-00007-1: Ultra-Low-Power ARM Cortex-M0+ MCU, 32 KB Flash, 1.8 to 3.6 V, -40 to 85 degC, 48-Pin LQFP, RoHS, Tray; VDD Max: 3.6 V; RAM: 8 KB; VDD Min: 1.8 V; Flash: 32 KB; Data EEPROM: 2 KB
U10 U11 = CMP-04892-000028-1: ANALOG SWITCH

## Sheet CommModule.SchDoc
size Legal; SheetNumber: 3; SheetTotal: 5
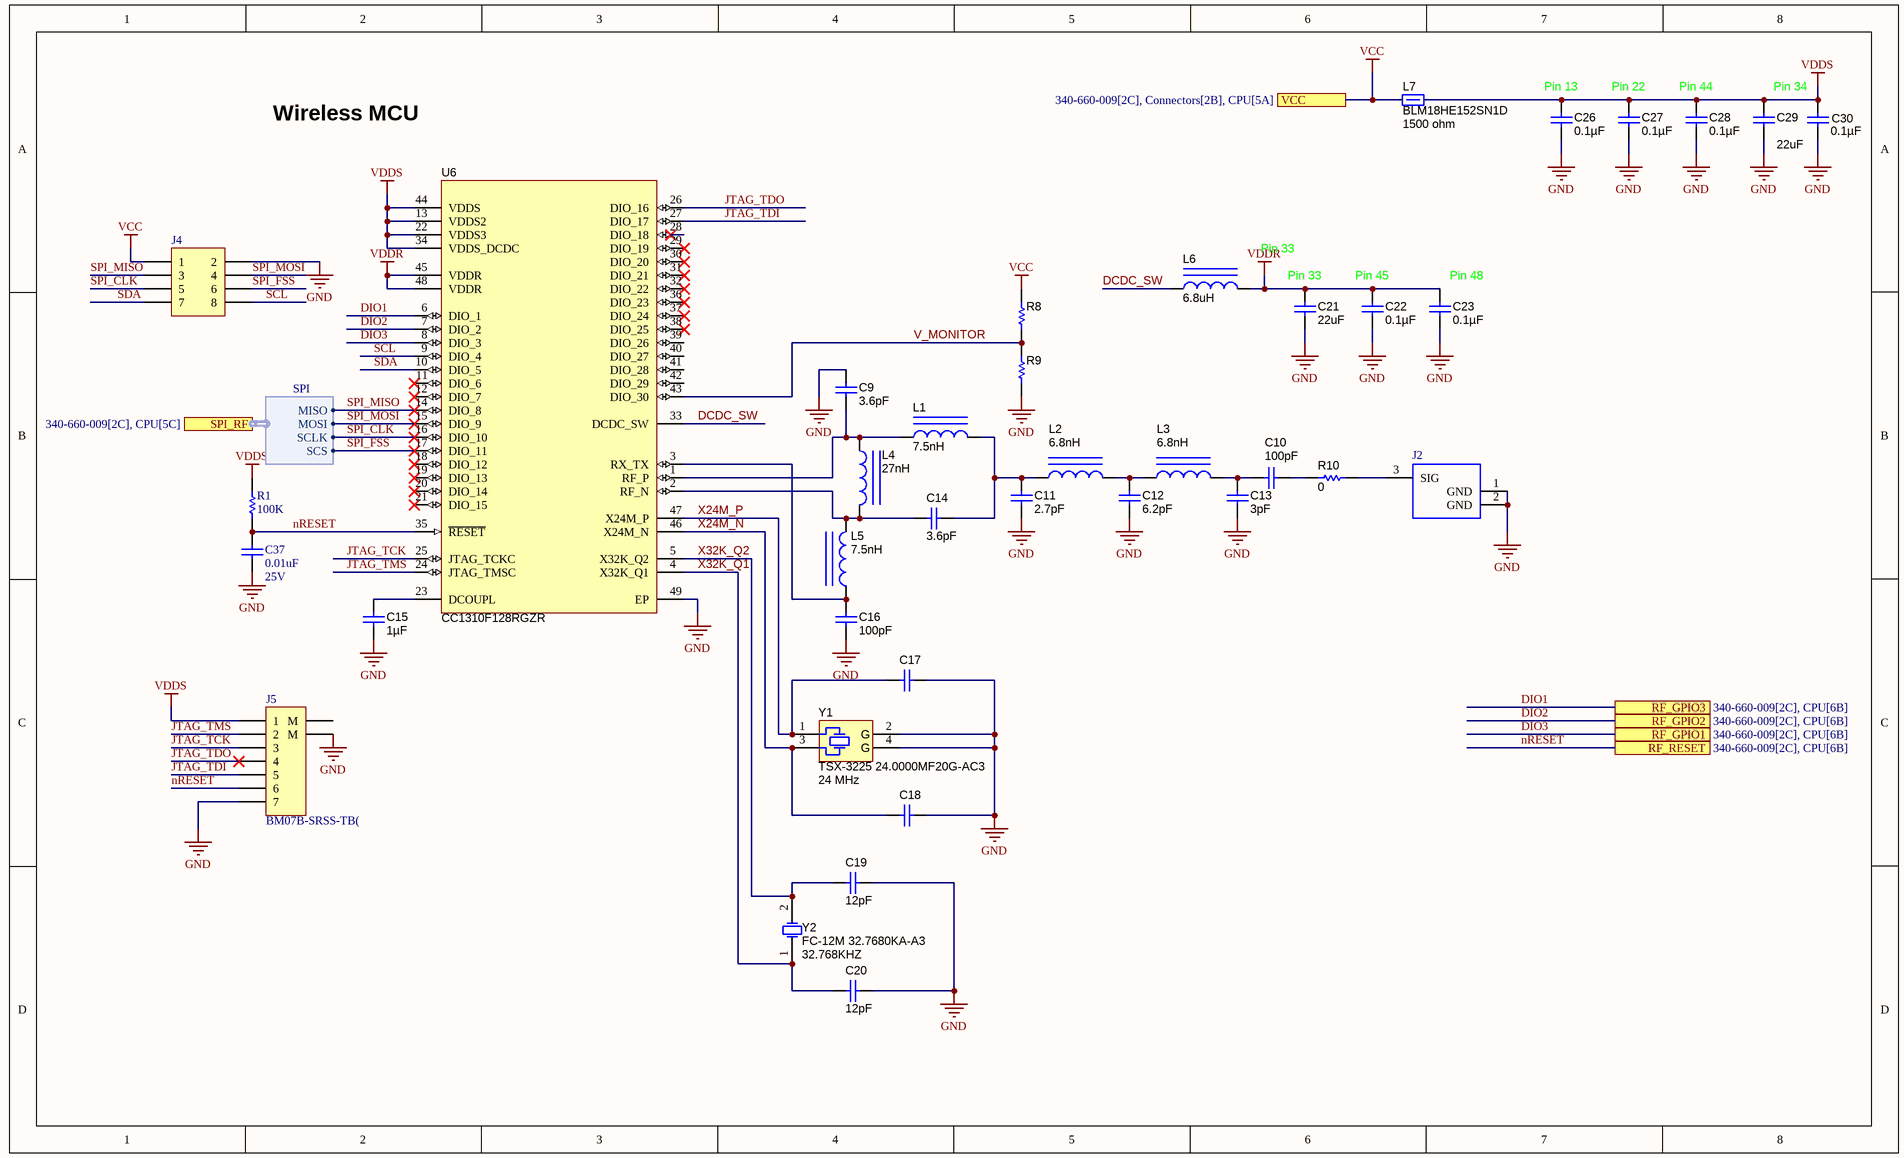
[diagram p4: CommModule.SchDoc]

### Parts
(Parts that share a designator on the sheet are numbered #1, #2 ... from top to bottom, then left to right.)
?  (no value)  (graphical)
C9  ValueDisplayed: 3.6pF  [0402]  (hidden comment: GRM1555C1H3R6CA01D)
C10  ValueDisplayed: 100pF  [0402]  (hidden comment: GRM1555C1H101JA01D)
C11  ValueDisplayed: 2.7pF  [0402]  (hidden comment: GRM1555C1H2R7CA01D)
C12  ValueDisplayed: 6.2pF  [0402]  (hidden comment: GRM1555C1H6R2CA01D)
C13  ValueDisplayed: 3pF  [0402]  (hidden comment: GRM1555C1H3R0CA01D)
C14  ValueDisplayed: 3.6pF  [0402]  (hidden comment: GRM1555C1H3R6CA01D)
C15  ValueDisplayed: 1µF  [0603]  (hidden comment: GRM188R70J105KA01D)
C16  ValueDisplayed: 100pF  [0402]  (hidden comment: GRM1555C1H101JA01D)
C17  Used in BOM report  [0603]  (value not drawn)
C18  Used in BOM report  [0603]  (value not drawn)
C19  ValueDisplayed: 12pF  [0603]  (hidden comment: 06035A120JAT2A)
C20  ValueDisplayed: 12pF  [0603]  (hidden comment: 06035A120JAT2A)
C21  ValueDisplayed: 22uF  [0603]  (hidden comment: GRM188R60J226MEA0D)
C22  ValueDisplayed: 0.1µF  [0402]  (hidden comment: GRM155R70J104KA01D)
C23  ValueDisplayed: 0.1µF  [0402]  (hidden comment: GRM155R70J104KA01D)
C26  ValueDisplayed: 0.1µF  [0402]  (hidden comment: GRM155R70J104KA01D)
C27  ValueDisplayed: 0.1µF  [0402]  (hidden comment: GRM155R70J104KA01D)
C28  ValueDisplayed: 0.1µF  [0402]  (hidden comment: GRM155R70J104KA01D)
C29  ValueDisplayed: 22uF  [0603]  (hidden comment: GRM188R60J226MEA0D)
C30  ValueDisplayed: 0.1µF  [0402]  (hidden comment: GRM155R70J104KA01D)
C37  value 0.01uF  Voltage: 25V  [0402CAP]  (hidden comment: ECJ-0EB1E103K)
J2#2  (no value)  [CONN_HRS-U.FL-R-SMT_V]
J4#2  (no value)  [CONN_SAMTEC_FTS-104-01-L-DV]
J5#2  BM07B-SRSS-TB(  [JST_BM07B_TOP]
L1  ValueDisplayed: 7.5nH  [IND_LQG15H]  (hidden comment: LQG15HS7N5J02D)
L2  value 6.8nH  [LQW15A_00_10]  (hidden comment: LQW15AN6N8G00D)
L3  value 6.8nH  [LQW15A_00_10]  (hidden comment: LQW15AN6N8G00D)
L4  ValueDisplayed: 27nH  [IND_LQG15H]  (hidden comment: LQG15HS27NJ02D)
L5  ValueDisplayed: 7.5nH  [IND_LQG15H]  (hidden comment: LQG15HS7N5J02D)
L6  ValueDisplayed: 6.8uH  [0805_HV]  (hidden comment: MLZ2012N6R8LT000)
L7  BLM18HE152SN1D  value 1500 ohm  [0603_950]
R1  value 100K  [0402RES]  (hidden comment: RC0402FR-07100KL)
R8#2  Used in BOM report  [0402]  (value not drawn)
R9#2  Used in BOM report  [0402]  (value not drawn)
R10#2  ValueDisplayed: 0  [0402]  (hidden comment: CRCW04020000Z0ED)
U6  CC1310F128RGZR  [RGZ0048A]
Y1  TSX-3225 24.0000MF20G-AC3  Frequency: 24 MHz  [EPSON_TSX-3225]
Y2  FC-12M 32.7680KA-A3  Frequency: 32.768KHZ  [Epson_FC-12M]

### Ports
RF_GPIO1 (see 340-660-009[2C], CPU[6B]), RF_GPIO2 (see 340-660-009[2C], CPU[6B]), RF_GPIO3 (see 340-660-009[2C], CPU[6B]), RF_RESET (see 340-660-009[2C], CPU[6B]), SPI_RF (harness SPI, see 340-660-009[2C], CPU[5C]), VCC (see 340-660-009[2C], Connectors[2B], CPU[5A])

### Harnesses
SPI: MISO, MOSI, SCLK, SCS

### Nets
GND: C9.1 C11.2 C12.2 C13.2 C15.1 C16.2 C17.2 C18.2 C19.1 C20.1 C21.2 C22.2 C23.2 C26.2 C27.2 C28.2 C29.2 C30.2 C37.1 J2#2.1(GND) J2#2.2(GND) J4#2.2 J5#2.7 J5#2.9(M) R9#2.1 U6.49(EP) Y1.2(GND) Y1.4(GND)
VCC: J4#2.1 L7.2 R8#2.2 ; port VCC  [project net V3.3V]
VDDR: C21.1 C22.1 C23.1 L6.2 U6.45(VDDR) U6.48(VDDR)
VDDS: C26.1 C27.1 C28.1 C29.1 C30.1 J5#2.1 L7.1 R1.2 U6.13(VDDS2) U6.22(VDDS3) U6.34(VDDS_DCDC) U6.44(VDDS)
DCDC_SW: L6.1 U6.33(DCDC_SW)
DIO1: U6.6(DIO_1) ; port RF_GPIO3
DIO2: U6.7(DIO_2) ; port RF_GPIO2
DIO3: U6.8(DIO_3) ; port RF_GPIO1
JTAG_TCK: J5#2.3 U6.25(JTAG_TCKC)
JTAG_TDI: J5#2.5 U6.27(DIO_17)
JTAG_TDO: J5#2.4 U6.26(DIO_16)
JTAG_TMS: J5#2.2 U6.24(JTAG_TMSC)
nRESET: C37.2 J5#2.6 R1.1 U6.35(~{RESET}) ; port RF_RESET
SCL: J4#2.8 U6.9(DIO_4)
SDA: J4#2.7 U6.10(DIO_5)
SPI_CLK: J4#2.5 U6.16(DIO_10) ; port SPI_RF.SCLK  [project net SPI2_SCK]
SPI_FSS: J4#2.6 U6.17(DIO_11) ; port SPI_RF.SCS  [project net SPI2_CS]
SPI_MISO: J4#2.3 U6.14(DIO_8) ; port SPI_RF.MISO  [project net SPI2_MISO]
SPI_MOSI: J4#2.4 U6.15(DIO_9) ; port SPI_RF.MOSI  [project net SPI2_MOSI]
V_MONITOR: R8#2.1 R9#2.2 U6.43(DIO_30)
X24M_N: C18.1 U6.46(X24M_N) Y1.3
X24M_P: C17.1 U6.47(X24M_P) Y1.1
X32K_Q1: C20.2 U6.4(X32K_Q1) Y2.1(OSC1)
X32K_Q2: C19.2 U6.5(X32K_Q2) Y2.2(OSC2)
NetC9_2: C9.2 L1.1 L4.1 U6.1(RF_P)
NetC10_1: C10.1 R10#2.1
NetC10_2: C10.2 C13.1 L3.2
NetC11_1: C11.1 C14.1 L1.2 L2.1
NetC12_1: C12.1 L2.2 L3.1
NetC14_2: C14.2 L4.2 L5.2 U6.2(RF_N)
NetC15_2: C15.2 U6.23(DCOUPL)
NetC16_1: C16.1 L5.1 U6.3(RX_TX)
NetJ2#2_3: J2#2.3(SIG) R10#2.2

Not connected (* = marked no-connect by the designer): J5#2 8(M); U6 11(DIO_6)* 12(DIO_7)* 18(DIO_12)* 19(DIO_13)* 20(DIO_14)* 21(DIO_15)* 28(DIO_18)* 29(DIO_19)* 30(DIO_20)* 31(DIO_21)* 32(DIO_22)* 36(DIO_23)* 37(DIO_24)* 38(DIO_25)* 39(DIO_26) 40(DIO_27) 41(DIO_28) 42(DIO_29)

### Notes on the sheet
- (near C26) Pin 13
- (near C27) Pin 22
- (near C28) Pin 44
- Pin 34
- Wireless MCU
- Pin 33
- (near C21) Pin 33
- (near C22) Pin 45
- (near C23) Pin 48

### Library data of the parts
? = ADSP_TitleBlock: ADSP Consulting TITLE BLOCK
C9 C14 = GRM1555C1H3R6CA01D: CAP, CERM, 3.6 pF, 50 V, +/- 5%, C0G/NP0, 0402; Manufacturer: MuRata; Polarized: N; CompType: Capacitor; Value: 3.6pF; U/M: EA; Cap_F: 0.0000000000036; Tolerance_%: 5; Value1: Unknown; VDC_V: 50; Value2: 50V; TaMin_C: -55; TaMax_C: 125
C10 = CMP-0006410-2: CAP, CERM, 100 pF, 50 V, +/- 5%, C0G/NP0, 0402; Manufacturer: MuRata; TaMin_C: -55°C; Polarized: N; SizeAreaWB_mm2: 3; Value1: Unknown; U/M: EA; Value: 100pF; TaMax_C: 125°C; SizeZ_mm: 0.6; SizeX_mm: 1; SizeY_mm: 0.5; Value2: 50V; CompType: Capacitor; AEC Category: Q200
C11 = CMP-0006450-2: CAP, CERM, 2.7 pF, 50 V, +/- 5%, C0G/NP0, 0402; Manufacturer: MuRata; TaMin_C: -55°C; Polarized: N; SizeAreaWB_mm2: 3; Value1: Unknown; U/M: EA; Value: 2.7pF; TaMax_C: 125°C; SizeZ_mm: 0.6; SizeX_mm: 1; SizeY_mm: 0.5; Value2: 50V; CompType: Capacitor; AEC Category: Q200
C12 = CMP-0006487-2: CAP, CERM, 6.2 pF, 50 V, +/- 5%, C0G/NP0, 0402; Manufacturer: MuRata; TaMin_C: -55°C; Polarized: N; SizeAreaWB_mm2: 3; Value1: Unknown; U/M: EA; Value: 6.2pF; TaMax_C: 125°C; SizeZ_mm: 0.6; SizeX_mm: 1; SizeY_mm: 0.5; Value2: 50V; CompType: Capacitor; AEC Category: Q200
C13 = CMP-0006460-2: CAP, CERM, 3 pF, 50 V, +/- 5%, C0G/NP0, 0402; Manufacturer: MuRata; TaMin_C: -55°C; Polarized: N; SizeAreaWB_mm2: 3; Value1: Unknown; U/M: EA; Value: 3pF; TaMax_C: 125°C; SizeZ_mm: 0.6; SizeX_mm: 1; SizeY_mm: 0.5; Value2: 50V; CompType: Capacitor; AEC Category: Q200
C15 = GRM188R70J105KA01D: CAP, CERM, 1 µF, 6.3 V, +/- 10%, X7R, 0603; Manufacturer: MuRata; Polarized: N; CompType: Capacitor; Value: 1uF; U/M: EA; Cap_F: 0.000001; Tolerance_%: 10; Value1: Unknown; VDC_V: 6.3; Value2: 6.3V; TaMin_C: -55; TaMax_C: 125
C16 = GRM1555C1H101JA01D: CAP, CERM, 100 pF, 50 V, +/- 5%, C0G/NP0, 0402; Manufacturer: MuRata; Polarized: N; CompType: Capacitor; Value: 100pF; U/M: EA; Cap_F: 0.0000000001; Tolerance_%: 5; Value1: Unknown; VDC_V: 50; Value2: 50V; TaMin_C: -55; TaMax_C: 125
C17 C18 = Capacitor: CAP, CERM, xxxF, xxV, [TempCo], xx%, [PackageReference]; Polarized: N; U/M: EA
C19 C20 = 06035A120JAT2A: CAP, CERM, 12 pF, 50 V, +/- 5%, C0G/NP0, 0603; Manufacturer: AVX; Polarized: N; CompType: Capacitor; Value: 12pF; U/M: EA; Cap_F: 0.000000000012; Tolerance_%: 5; ESR_ohm: 0.363; Value1: 0.363 ohm; VDC_V: 50; Value2: 50V; TaMin_C: -55; TaMax_C: 125
C21 C29 = CMP-0007306-5: CAP, CERM, 22 uF, 6.3 V, +/- 20%, X5R, 0603; Manufacturer: MuRata; TaMin_C: -55°C; Polarized: N; SizeAreaWB_mm2: 4.68; Value1: Unknown; U/M: EA; Value: 22uF; TaMax_C: 85°C; SizeZ_mm: 1; SizeX_mm: 1.6; SizeY_mm: 0.8; Value2: 6.3V; SizeArea_mm2: 1.28; CompType: Capacitor; Cap_F: 22µF; AEC Category: Q200
C22 C23 C26-C28 C30 = GRM155R70J104KA01D: CAP, CERM, 0.1 µF, 6.3 V, +/- 10%, X7R, 0402; Manufacturer: MuRata; Polarized: N; CompType: Capacitor; Value: 0.1uF; U/M: EA; Cap_F: 0.0000001; Tolerance_%: 10; Value1: Unknown; VDC_V: 6.3; Value2: 6.3V; TaMin_C: -55; TaMax_C: 125
C37 = CAP_0402_0.01uF_X7R_25V_2: as C7 on sheet CPU
J2#2 = CONN_Hirose_U.FL-R-SMT(10): Ultra Small Surface Mount Coaxial Connector, 50 Ohm, -40 to 90 degC, 3-Pin SMD, RoHS, Tape and Reel; ADSP_PN: 03000-233; Current Rating: 3 A; Mfg: Hirose
J4#2 = CONN_Samtec_FTS-104-01-L-DV: as J1 on sheet Connectors
J5#2 = CONN_JST-BM07B-SRSS-TB: CONN HEADER SH 7POS TOP 1MM TIN; Positions: 7; Mfg: JST; ADSP_PN: 03000-???
L1 L5 = CMP-0058643-1: Inductor, Multilayer, Air Core, 7.5 nH, 0.3 A, 0.24 ohm, SMD; Manufacturer: MuRata; Isat: 0.3A @ % inductance drop; Irms: 0.3A @ C rise; Green_Lifecycle: Active; SizeAreaWB_mm2: 3; DCR_ohm: 2.4d; Green_REACh: Passed; Value: 7.5nH; Imax_A: 3dA; SizeZ_mm: 0.55; SizeX_mm: 1; SizeY_mm: 0.5; Value2: 0.3A; AEC Category: Q200
L2 L3 = LQW15AN6N8G00D: Inductor, Wirewound, 6.8 nH, 0.7 A, 0.09 ohm, SMD; Manufacturer: MuRata; Ind_H: 6.8E-9; Imax_A: 0.7; DCR_ohm: 0.09; Value2: 0.7A
L4 = CMP-0058623-1: Inductor, Multilayer, Air Core, 27 nH, 0.3 A, 0.46 ohm, SMD; Manufacturer: MuRata; Isat: 0.3A @ % inductance drop; Irms: 0.3A @ C rise; Green_Lifecycle: Active; SizeAreaWB_mm2: 3; DCR_ohm: 4.6d; Green_REACh: Passed; Value: 27nH; Imax_A: 3dA; SizeZ_mm: 0.55; SizeX_mm: 1; SizeY_mm: 0.5; Value2: 0.3A; AEC Category: Q200
L6 = CMP-0062727-1: Inductor, Multilayer, Ferrite, 6.8 uH, 0.11 A, 0.25 ohm, SMD; Manufacturer: TDK; Isat: 0.11A @ 50% inductance drop; Irms: 0.55A @ 20C rise; Green_Lifecycle: Active; SizeAreaWB_mm2: 6.75; DCR_ohm: 2.5d; Green_REACh: Passed; Value: 6.8uH; Imax_A: 1.1dA; SizeZ_mm: 1.45; SizeX_mm: 2; SizeY_mm: 1.25; Value2: 0.11A; SizeArea_mm2: 2.5; Ind_H: 6.8µH; AEC Category: Q200
L7 = BLM18HE152SN1D: Ferrite Bead, 1500 ohm @ 100 MHz, 0.5 A, 0603_950; Manufacturer: MuRata; Imax_A: 0.5; Value1: 0.5 ohm; Value2: 0.5A; ZTyp@100MHz_Ohm: 1500
R1 = Res_0402_100K_1%: as R2 on sheet CPU
R8#2 R9#2 = Resistor: RES, xxx ohm, x%, xW, [PackageReference]; U/M: EA
R10#2 = CRCW04020000Z0ED: RES, 0, 5%, 0.063 W, 0402; Manufacturer: Vishay-Dale; CompType: Resistor; Value: 0; Value_Code: 0000; Tolerance_%: 5; Power_W: 0.063; Value2: 0.063W; VDC_V: 50; TempCo: 200 ppm/C; EIA_Code: E24; U/M: EA
U6 = CC1310F128RGZR: Sub-1 GHz and 2.4 GHz Multi-standard RF IC Family, RGZ0048A; Alternate PartNumber: CC1310F128RGZT; Manufacturer: Texas Instruments; SymbolCreator: Altium; U/M: EA
Y1 = TSX-3225 24.0000MF20G-AC3: Crystal, 24 MHz, 9 pF, SMD; Manufacturer: Epson; SymbolCreator: a0412235; U/M: EA; TaMin_C: -40; TaMax_C: 85; Frequency Stability: ±20ppm
Y2 = FC-12M 32.7680KA-A3: Crystal, 32.768kHz, 12.5pF, SMD; Manufacturer: Epson; SymbolCreator: a0412235; U/M: EA; TaMin_C: -40; TaMax_C: 85; Frequency Stability: ±20ppm

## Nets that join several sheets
GND: 340-660-009 (6 pins), 1 (J2#1.7), 2 (J3#1.7), 3 (J4#1.7), 4 (J5#1.7), 5 (J6.7), 6 (J7.7), 7 (J8.7), 8 (J9.7), 9 (J10.7), 10 (J11.7), 11 (J12.7), 12 (J13.7), 13 (J14.7), 14 (J15.7), 15 (J16.7), 16 (J17.7), 17 (J18.7), 18 (J19.7), 19 (J20.7), 20 (J21.7), 21 (J22.7), 22 (J23.7), 23 (J24.7), 24 (J25.7), 25 (J26.7), 26 (J27.7), 27 (J28.7), 28 (J29.7), 29 (J30.7), 30 (J31.7), 31 (J32.7), 32 (J33.7), 33 (J34.7), 34 (J35.7), 35 (J36.7), 36 (J37.7), 37 (J38.7), 38 (J39.7), 39 (J40.7), 40 (J41.7), 41 (J42.7), 42 (J43.7), 43 (J44.7), 44 (J45.7), 45 (J46.7), 46 (J47.7), 47 (J48.7), 48 (J49.7), 49 (J51.7), CPU (32 pins), CommModule (28 pins)
HARV_IN: 340-660-009 (C1.+ TP1.1), 1 (R4#1.2), 2 (R5#1.2), 3 (R6.2), 4 (R7.2), 5 (R8#1.2), 6 (R9#1.2), 7 (R10#1.2), 8 (R11.2), 9 (R12.2), 10 (R13.2), 11 (R14.2), 12 (R15.2), 13 (R16.2), 14 (R17.2), 15 (R18.2), 16 (R19.2), 17 (R20.2), 18 (R21.2), 19 (R22.2), 20 (R23.2), 21 (R24.2), 22 (R25.2), 23 (R26.2), 24 (R27.2), 25 (R28.2), 26 (R29.2), 27 (R30.2), 28 (R31.2), 29 (R32.2), 30 (R33.2), 31 (R34.2), 32 (R35.2), 33 (R36.2), 34 (R37.2), 35 (R38.2), 36 (R39.2), 37 (R40.2), 38 (R41.2), 39 (R42.2), 40 (R43.2), 41 (R44.2), 42 (R45.2), 43 (R46.2), 44 (R47.2), 45 (R48.2), 46 (R49.2), 47 (R50.2), 48 (R51.2), 49 (R56.2), CPU (R3.2)
V3.3V: 340-660-009 (C2.2 SJ1.2 U4.3 U4.8), 1 (J2#1.4), 2 (J3#1.4), 3 (J4#1.4), 4 (J5#1.4), 5 (J6.4), 6 (J7.4), 7 (J8.4), 8 (J9.4), 9 (J10.4), 10 (J11.4), 11 (J12.4), 12 (J13.4), 13 (J14.4), 14 (J15.4), 15 (J16.4), 16 (J17.4), 17 (J18.4), 18 (J19.4), 19 (J20.4), 20 (J21.4), 21 (J22.4), 22 (J23.4), 23 (J24.4), 24 (J25.4), 25 (J26.4), 26 (J27.4), 27 (J28.4), 28 (J29.4), 29 (J30.4), 30 (J31.4), 31 (J32.4), 32 (J33.4), 33 (J34.4), 34 (J35.4), 35 (J36.4), 36 (J37.4), 37 (J38.4), 38 (J39.4), 39 (J40.4), 40 (J41.4), 41 (J42.4), 42 (J43.4), 43 (J44.4), 44 (J45.4), 45 (J46.4), 46 (J47.4), 47 (J48.4), 48 (J49.4), 49 (J51.4), CPU (24 pins), CommModule (J4#2.1 L7.2 R8#2.2)
DIO1: CPU (U5.22), CommModule (U6.6)
DIO2: CPU (U5.21), CommModule (U6.7)
DIO3: CPU (U5.46), CommModule (U6.8)
MUXA: 1 (J2#1.6), CPU (U7.19)
MUXA: 2 (J3#1.6), CPU (U7.20)
MUXA: 3 (J4#1.6), CPU (U7.21)
MUXA: 4 (J5#1.6), CPU (U7.22)
MUXA: 5 (J6.6), CPU (U7.23)
MUXA: 6 (J7.6), CPU (U7.24)
MUXA: 7 (J8.6), CPU (U7.25)
MUXA: 8 (J9.6), CPU (U7.26)
MUXA: 9 (J10.6), CPU (U7.11)
MUXA: 10 (J11.6), CPU (U7.10)
MUXA: 11 (J12.6), CPU (U7.9)
MUXA: 12 (J13.6), CPU (U7.8)
MUXA: 13 (J14.6), CPU (U7.7)
MUXA: 14 (J15.6), CPU (U7.6)
MUXA: 15 (J16.6), CPU (U7.5)
MUXA: 16 (J17.6), CPU (U7.4)
MUXA: 17 (J18.6), CPU (U8.19)
MUXA: 18 (J19.6), CPU (U8.20)
MUXA: 19 (J20.6), CPU (U8.21)
MUXA: 20 (J21.6), CPU (U8.22)
MUXA: 21 (J22.6), CPU (U8.23)
MUXA: 22 (J23.6), CPU (U8.24)
MUXA: 23 (J24.6), CPU (U8.25)
MUXA: 24 (J25.6), CPU (U8.26)
MUXA: 25 (J26.6), CPU (U8.11)
MUXA: 26 (J27.6), CPU (U8.10)
MUXA: 27 (J28.6), CPU (U8.9)
MUXA: 28 (J29.6), CPU (U8.8)
MUXA: 29 (J30.6), CPU (U8.7)
MUXA: 30 (J31.6), CPU (U8.6)
MUXA: 31 (J32.6), CPU (U8.5)
MUXA: 32 (J33.6), CPU (U8.4)
MUXA: 33 (J34.6), CPU (U9.19)
MUXA: 34 (J35.6), CPU (U9.20)
MUXA: 35 (J36.6), CPU (U9.21)
MUXA: 36 (J37.6), CPU (U9.22)
MUXA: 37 (J38.6), CPU (U9.23)
MUXA: 38 (J39.6), CPU (U9.24)
MUXA: 39 (J40.6), CPU (U9.25)
MUXA: 40 (J41.6), CPU (U9.26)
MUXA: 41 (J42.6), CPU (U9.11)
MUXA: 42 (J43.6), CPU (U9.10)
MUXA: 43 (J44.6), CPU (U9.9)
MUXA: 44 (J45.6), CPU (U9.8)
MUXA: 45 (J46.6), CPU (U9.7)
MUXA: 46 (J47.6), CPU (U9.6)
MUXA: 47 (J48.6), CPU (U9.5)
MUXA: 48 (J49.6), CPU (U9.4)
MUXA: 49 (J51.6), CPU (U10.2)
MUXB1: 1 (J2#1.5), CPU (U1.19)
MUXB2: 2 (J3#1.5), CPU (U1.20)
MUXB3: 3 (J4#1.5), CPU (U1.21)
MUXB4: 4 (J5#1.5), CPU (U1.22)
MUXB5: 5 (J6.5), CPU (U1.23)
MUXB6: 6 (J7.5), CPU (U1.24)
MUXB7: 7 (J8.5), CPU (U1.25)
MUXB8: 8 (J9.5), CPU (U1.26)
MUXB9: 9 (J10.5), CPU (U1.11)
MUXB10: 10 (J11.5), CPU (U1.10)
MUXB11: 11 (J12.5), CPU (U1.9)
MUXB12: 12 (J13.5), CPU (U1.8)
MUXB13: 13 (J14.5), CPU (U1.7)
MUXB14: 14 (J15.5), CPU (U1.6)
MUXB15: 15 (J16.5), CPU (U1.5)
MUXB16: 16 (J17.5), CPU (U1.4)
MUXB17: 17 (J18.5), CPU (U2.19)
MUXB18: 18 (J19.5), CPU (U2.20)
MUXB19: 19 (J20.5), CPU (U2.21)
MUXB20: 20 (J21.5), CPU (U2.22)
MUXB21: 21 (J22.5), CPU (U2.23)
MUXB22: 22 (J23.5), CPU (U2.24)
MUXB23: 23 (J24.5), CPU (U2.25)
MUXB24: 24 (J25.5), CPU (U2.26)
MUXB25: 25 (J26.5), CPU (U2.11)
MUXB26: 26 (J27.5), CPU (U2.10)
MUXB27: 27 (J28.5), CPU (U2.9)
MUXB28: 28 (J29.5), CPU (U2.8)
MUXB29: 29 (J30.5), CPU (U2.7)
MUXB30: 30 (J31.5), CPU (U2.6)
MUXB31: 31 (J32.5), CPU (U2.5)
MUXB32: 32 (J33.5), CPU (U2.4)
MUXB33: 33 (J34.5), CPU (U3.19)
MUXB34: 34 (J35.5), CPU (U3.20)
MUXB35: 35 (J36.5), CPU (U3.21)
MUXB36: 36 (J37.5), CPU (U3.22)
MUXB37: 37 (J38.5), CPU (U3.23)
MUXB38: 38 (J39.5), CPU (U3.24)
MUXB39: 39 (J40.5), CPU (U3.25)
MUXB40: 40 (J41.5), CPU (U3.26)
MUXB41: 41 (J42.5), CPU (U3.11)
MUXB42: 42 (J43.5), CPU (U3.10)
MUXB43: 43 (J44.5), CPU (U3.9)
MUXB44: 44 (J45.5), CPU (U3.8)
MUXB45: 45 (J46.5), CPU (U3.7)
MUXB46: 46 (J47.5), CPU (U3.6)
MUXB47: 47 (J48.5), CPU (U3.5)
MUXB48: 48 (J49.5), CPU (U3.4)
MUXB49: 49 (J51.5), CPU (U11.2)
nRESET: CPU (U5.19), CommModule (C37.2 J5#2.6 R1.1 U6.35)
SPI2_CS: CPU (U5.25), CommModule (J4#2.6 U6.17)
SPI2_MISO: CPU (U5.27), CommModule (J4#2.3 U6.14)
SPI2_MOSI: CPU (U5.28), CommModule (J4#2.4 U6.15)
SPI2_SCK: CPU (U5.26), CommModule (J4#2.5 U6.16)
SPI_MISO: 1 (J2#1.3), 2 (J3#1.3), 3 (J4#1.3), 4 (J5#1.3), 5 (J6.3), 6 (J7.3), 7 (J8.3), 8 (J9.3), 9 (J10.3), 10 (J11.3), 11 (J12.3), 12 (J13.3), 13 (J14.3), 14 (J15.3), 15 (J16.3), 16 (J17.3), 17 (J18.3), 18 (J19.3), 19 (J20.3), 20 (J21.3), 21 (J22.3), 22 (J23.3), 23 (J24.3), 24 (J25.3), 25 (J26.3), 26 (J27.3), 27 (J28.3), 28 (J29.3), 29 (J30.3), 30 (J31.3), 31 (J32.3), 32 (J33.3), 33 (J34.3), 34 (J35.3), 35 (J36.3), 36 (J37.3), 37 (J38.3), 38 (J39.3), 39 (J40.3), 40 (J41.3), 41 (J42.3), 42 (J43.3), 43 (J44.3), 44 (J45.3), 45 (J46.3), 46 (J47.3), 47 (J48.3), 48 (J49.3), 49 (J51.3), CPU (U5.40)
SPI_SCLK: 1 (J2#1.1), 2 (J3#1.1), 3 (J4#1.1), 4 (J5#1.1), 5 (J6.1), 6 (J7.1), 7 (J8.1), 8 (J9.1), 9 (J10.1), 10 (J11.1), 11 (J12.1), 12 (J13.1), 13 (J14.1), 14 (J15.1), 15 (J16.1), 16 (J17.1), 17 (J18.1), 18 (J19.1), 19 (J20.1), 20 (J21.1), 21 (J22.1), 22 (J23.1), 23 (J24.1), 24 (J25.1), 25 (J26.1), 26 (J27.1), 27 (J28.1), 28 (J29.1), 29 (J30.1), 30 (J31.1), 31 (J32.1), 32 (J33.1), 33 (J34.1), 34 (J35.1), 35 (J36.1), 36 (J37.1), 37 (J38.1), 38 (J39.1), 39 (J40.1), 40 (J41.1), 41 (J42.1), 42 (J43.1), 43 (J44.1), 44 (J45.1), 45 (J46.1), 46 (J47.1), 47 (J48.1), 48 (J49.1), 49 (J51.1), CPU (U5.39)

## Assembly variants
Base: all parts fitted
